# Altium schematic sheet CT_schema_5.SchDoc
size 279 x 211 mm
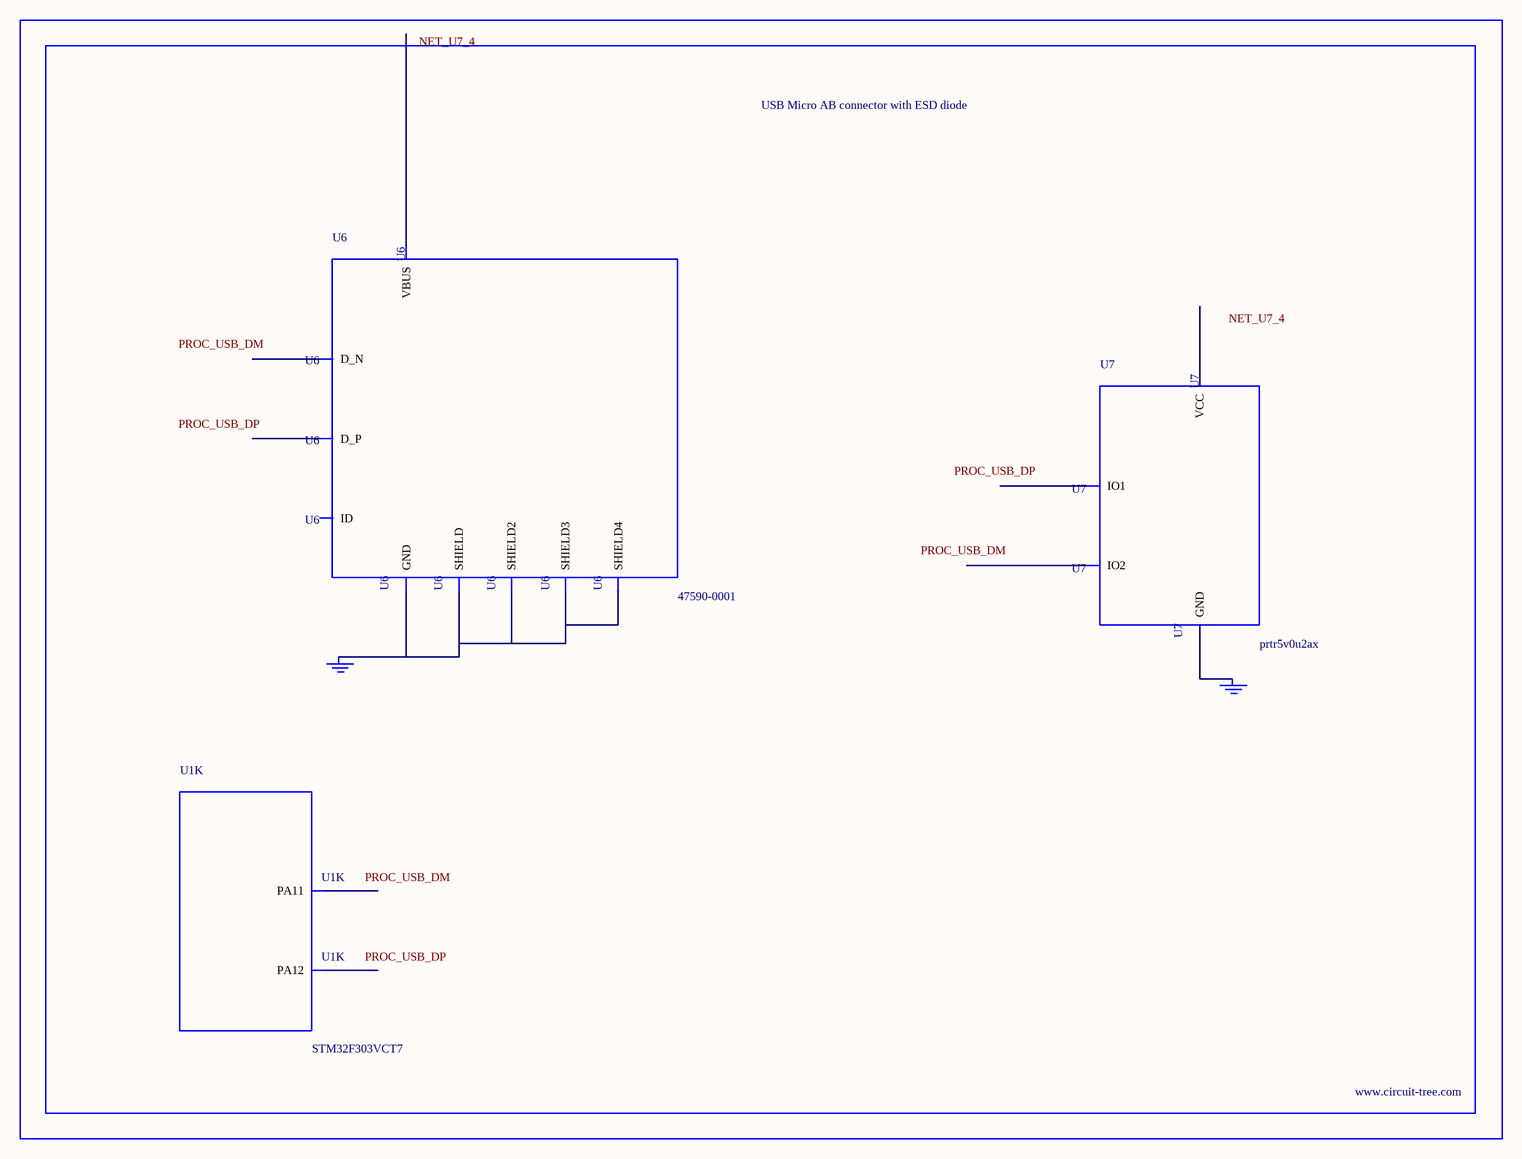
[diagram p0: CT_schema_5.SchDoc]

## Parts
BORDER4  (no value)
GND_INSTANCE_4_0  (no value)
GND_INSTANCE_4_1  (no value)
U1  STM32F303VCT7  [LQFP100]  (part K of 11)
U6  47590-0001  [MICRO_USB_AB]
U7  prtr5v0u2ax  [SOT143B]

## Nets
NetGND_INSTANCE_4_0_0: GND_INSTANCE_4_0.0(GND) U6.5(GND) U6.6(SHIELD) U6.7(SHIELD2) U6.8(SHIELD3) U6.9(SHIELD4)
NetGND_INSTANCE_4_1_0: GND_INSTANCE_4_1.0(GND) U7.1(GND)

Not connected (* = marked no-connect by the designer): U1 70(PA11) 71(PA12); U6 1(VBUS) 2(D_N) 3(D_P) 4(ID); U7 2(IO1) 3(IO2) 4(VCC)

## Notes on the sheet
- Labels drawn without touching a wire or pin: NET_U7_4, PROC_USB_DM, PROC_USB_DP

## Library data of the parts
BORDER4 = BORDER_PAGE4
GND_INSTANCE_4_0 GND_INSTANCE_4_1 = GND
